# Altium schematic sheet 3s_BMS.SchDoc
size A4; SheetNumber: 1; SheetTotal: 2
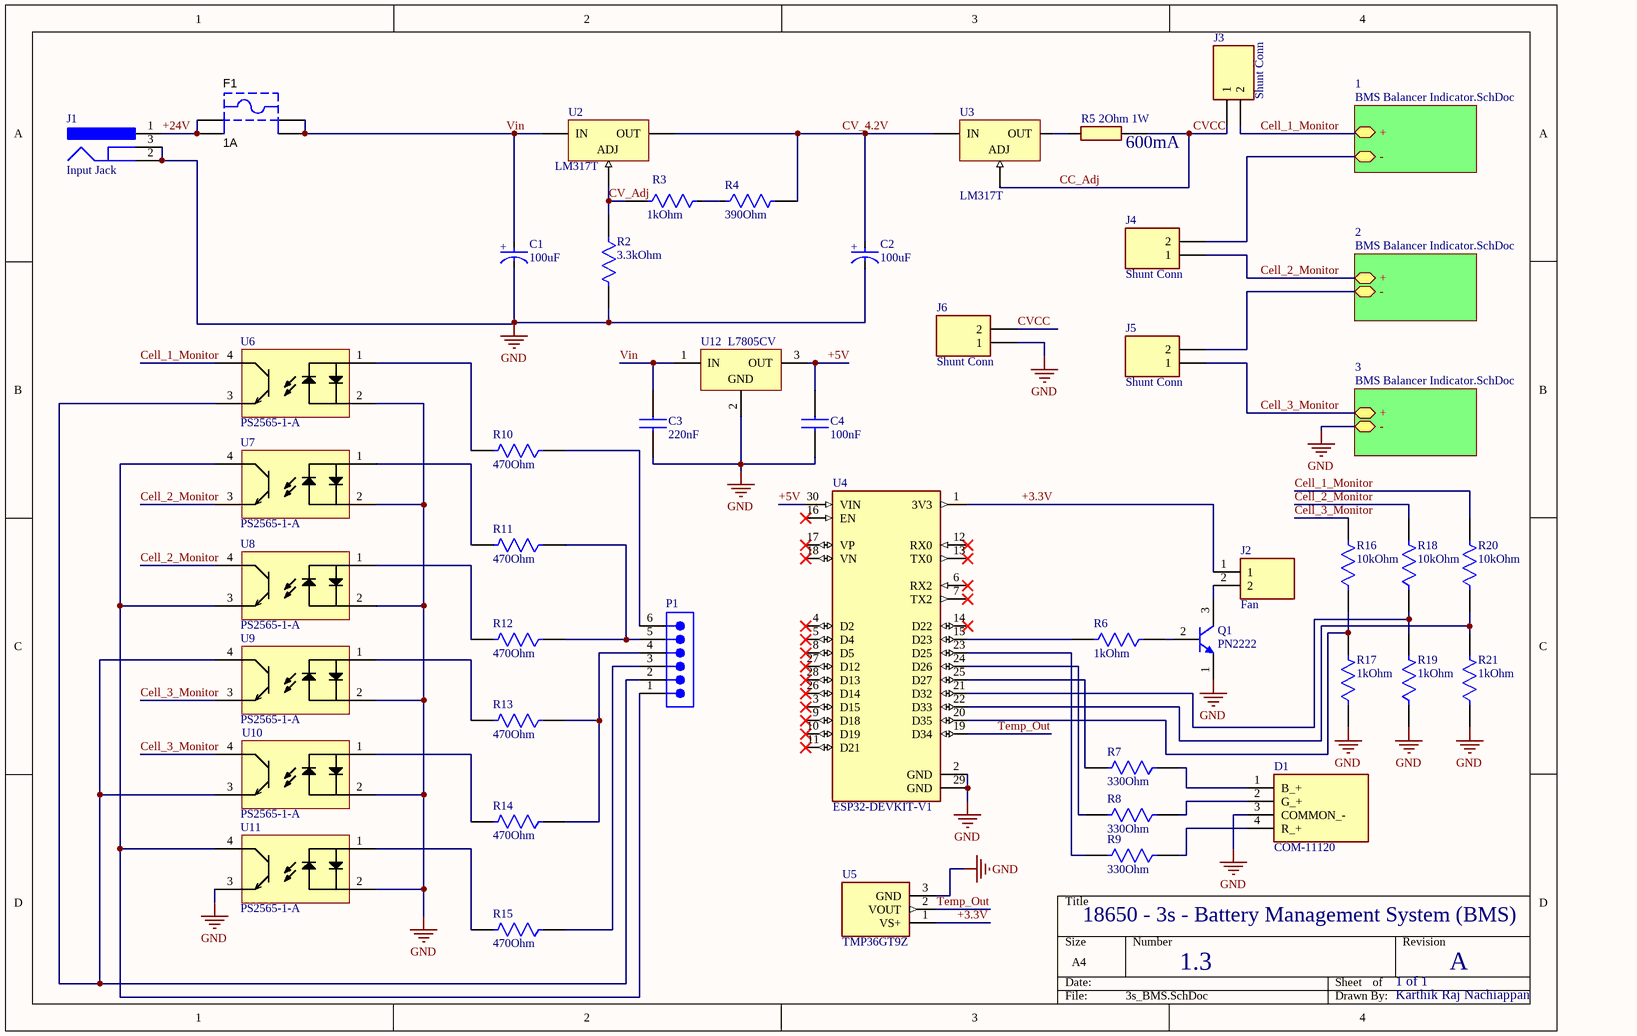
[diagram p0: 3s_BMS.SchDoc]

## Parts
C1  100uF  [FP-RAD-TH-D_8_0_5-L_11_5-MFG]
C2  100uF  [FP-RAD-TH-D_8_0_5-L_11_5-MFG]
C3  220nF  [K224K20X7RF5TH5]
C4  100nF  [C322C104K1R5TA]
D1  COM-11120  [COM11120]
F1  1A  [KSTN-3557-2]
J1  Input Jack  [CUI-PJ-002A_V]
J2  Fan  [HDRV2W67P0X254_1X2_467X234X823P]
J3  Shunt Conn  [HDRV2W67P0X254_1X2_467X234X823P]
J4  Shunt Conn  [HDRV2W67P0X254_1X2_467X234X823P]
J5  Shunt Conn  [HDRV2W67P0X254_1X2_467X234X823P]
J6  Shunt Conn  [HDRV2W67P0X254_1X2_467X234X823P]
P1  (no value)  [SMTC-TSW-106-07-X-S]
Q1  PN2222  [FAIR-TO-92-3]
R2  3.3kOhm  [FP-MRS25-MFG]
R3  1kOhm  [FP-MRS25-MFG]
R4  390Ohm  [FP-MRS25-MFG]
R5  2Ohm 1W  [RESAD1650W63L650D250]
R6  1kOhm  [FP-MRS25-MFG]
R7  330Ohm  [FP-MRS25-MFG]
R8  330Ohm  [FP-MRS25-MFG]
R9  330Ohm  [FP-MRS25-MFG]
R10  470Ohm  [FP-MRS25-MFG]
R11  470Ohm  [FP-MRS25-MFG]
R12  470Ohm  [FP-MRS25-MFG]
R13  470Ohm  [FP-MRS25-MFG]
R14  470Ohm  [FP-MRS25-MFG]
R15  470Ohm  [FP-MRS25-MFG]
R16  10kOhm  [FP-MRS25-MFG]
R17  1kOhm  [FP-MRS25-MFG]
R18  10kOhm  [FP-MRS25-MFG]
R19  1kOhm  [FP-MRS25-MFG]
R20  10kOhm  [FP-MRS25-MFG]
R21  1kOhm  [FP-MRS25-MFG]
U2  LM317T  [TO-220]
U3  LM317T  [TO-220]
U4  ESP32-DEVKIT-V1  [MODULE_ESP32_DEVKIT_V1]
U5  TMP36GT9Z  [TO-92]
U6  PS2565-1-A  [DIP762W50P254L460H455Q4B]
U7  PS2565-1-A  [DIP762W50P254L460H455Q4B]
U8  PS2565-1-A  [DIP762W50P254L460H455Q4B]
U9  PS2565-1-A  [DIP762W50P254L460H455Q4B]
U10  PS2565-1-A  [DIP762W50P254L460H455Q4B]
U11  PS2565-1-A  [DIP762W50P254L460H455Q4B]
U12  L7805CV  [TO220]

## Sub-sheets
1 = BMS Balancer Indicator.SchDoc: + (bidir), - (bidir)
2 = BMS Balancer Indicator.SchDoc: + (bidir), - (bidir)
3 = BMS Balancer Indicator.SchDoc: + (bidir), - (bidir)

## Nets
GND: C1.1(C) C2.1(C) C3.2 C4.2(-) D1.3(COMMON_-) J1.2 J1.3 J6.1 Q1.1(E) R2.2 R17.1 R19.1 R21.1 U4.2(GND) U4.29(GND) U5.3(GND) U6.2(Cathode) U7.2(Cathode) U8.2(Cathode) U9.2(Cathode) U10.2(Cathode) U11.2(Cathode) U11.3(Emitter) U12.2(GND) ; sheet 3/-
+3.3V: J2.1 U4.1(3V3) U5.1(VS+)
+5V: C4.1(+) U4.30(VIN) U12.3(OUT)
+24V: F1.1 F1.2 J1.1
CC_Adj: J3.1 J6.2 R5.2 U3.1(ADJ)  [also labelled CVCC]
Cell_1_Monitor: J3.2 R20.2 U6.4(Collector) ; sheet 1/+
Cell_2_Monitor: J4.1 R18.2 U7.3(Emitter) U8.4(Collector) ; sheet 2/+
Cell_3_Monitor: J5.1 R16.2 U9.3(Emitter) U10.4(Collector) ; sheet 3/+
CV_4.2V: C2.2(A) R4.2 U2.2(OUT) U3.3(IN)
CV_Adj: R2.1 R3.1 U2.1(ADJ)
Temp_Out: U4.19(D34) U5.2(VOUT)
Vin: C1.2(A) C3.1 F1.3 F1.4 U2.3(IN) U12.1(IN)
NetD1_1: D1.1(B_+) R7.1
NetD1_2: D1.2(G_+) R8.1
NetD1_4: D1.4(R_+) R9.1
NetJ2_2: J2.2 Q1.3(C)
NetJ4_2: J4.2 ; sheet 1/-
NetJ5_2: J5.2 ; sheet 2/-
NetP1_1: P1.1 U7.4(Collector) U8.3(Emitter) U11.4(Collector)
NetP1_2: P1.2 U6.3(Emitter) U9.4(Collector) U10.3(Emitter)
NetP1_3: P1.3 R15.1
NetP1_4: P1.4 R13.1 R14.1
NetP1_5: P1.5 R11.1 R12.1
NetP1_6: P1.6 R10.1
NetQ1_2: Q1.2(B) R6.1
NetR3_2: R3.2 R4.1
NetR5_1: R5.1 U3.2(OUT)
NetR6_2: R6.2 U4.15(D23)
NetR7_2: R7.2 U4.25(D27)
NetR8_2: R8.2 U4.24(D26)
NetR9_2: R9.2 U4.23(D25)
NetR10_2: R10.2 U6.1(Anode)
NetR11_2: R11.2 U7.1(Anode)
NetR12_2: R12.2 U8.1(Anode)
NetR13_2: R13.2 U9.1(Anode)
NetR14_2: R14.2 U10.1(Anode)
NetR15_2: R15.2 U11.1(Anode)
NetR16_1: R16.1 R17.2 U4.20(D35)
NetR18_1: R18.1 R19.2 U4.21(D32)
NetR20_1: R20.1 R21.2 U4.22(D33)

Not connected (* = marked no-connect by the designer): U4 3(D15)* 4(D2)* 5(D4)* 6(RX2)* 7(TX2)* 8(D5)* 9(D18)* 10(D19)* 11(D21)* 12(RX0)* 13(TX0)* 14(D22)* 16(EN)* 17(VP)* 18(VN)* 26(D14)* 27(D12)* 28(D13)*

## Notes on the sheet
- (near R5) 600mA
- 18650 - 3s - Battery Management System (BMS)
- 1.3
- 1 of 1
- A
- Karthik Raj Nachiappan

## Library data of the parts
C1 C2 = CMP-05427-001978-1: Aluminum Electrolytic Capacitors (Radial Lead Type) 100uF ±20% 50V
C3 = K224K20X7RF5TH5: Capacitor; Manufacturer_Name: Vishay
C4 = C322C104M5U5TA: Capacitor; Manufacturer_Name: KEMET
D1 = COM-11120: LED; Manufacturer_Name: SparkFun
F1 = CMP-2000-05461-1: FUSE HOLDER, PCB MOUNT, 500VAC, 20A, ROHS; Manufacturer: Keystone-Electronics; Number of Circuits: 1; Voltage: 500V; Fuseholder Type: Block; Fuse Type: Blade; Fuse Size: 0.43"Lx0.15"Wx0.64"H(10.92mmx3.81mmx16.25mm); For Use With/Related Products: ATC,ATO257,MINI897; Current Rating: 30A
J1 = CMP-2000-06895-2: Through Hole Right Angle DC Power Jack, 2.5 A, 2 mm Center Pin, 3 Position, -25 to 85 degC, RoHS, Bulk; Manufacturer: CUIInc.; Brand: CUI; Inside Contact Diameter: 2mm; Voltage Rating: 24V; Outside Contact Diameter: 6.5mm; Current Rating: 2.5A; Insulation Resistance: 50MOhms
J2-J6 = 5-146277-2: Connector; Manufacturer_Name: TE Connectivity
P1 = CMP-1024-00383-1: 0.025" SQ Post Header, Through-hole, Vertical, -55 to 125 degC, 2.54 mm Pitch, 6-Pin, Male, RoHS; Manufacturer: Samtec; PartNumber: TSW-106-07-G-S; Pitch: 2.54 mm
Q1 = CMP-2000-06911-1: NPN General-Purpose Amplifier, 40 V, -55 to 150 degC, 3-Pin TO-92, RoHS, Tape and Reel; Manufacturer: FairchildSemiconductor; Configuration: Single; Collector-Emitter Saturation Voltage: 1V; Collector- Emitter Voltage VCEO Max: 40V; Unit Weight: 0.008466oz; Maximum DC Collector Current: 1A; DC Collector/Base Gain hfe Min: 100; Emitter- Base Voltage VEBO: 6V; Maximum Power Dissipation: 625mW; DC Current Gain hFE Max: 300; Gain Bandwidth Product fT: 300MHz; Collector- Base Voltage VCBO: 75V
R2-R4 R6-R21 = CMP-02408-000051-1: RES 1K OHM 0.6W 1% AXIAL; Power Rating: 600mW; Lead Diameter: 0.6mm; Voltage Rating (DC): 350V; Resistance: 1kR; Temperature Coefficient: 50ppm/°C
R5 = PR01000102008JR500: Resistor; Manufacturer_Name: Vishay
U2 U3 = CMP-0244-00444-1: 1.5A, 1.2V to 37V Adjustable Voltage Regulator, 3-Pin TO-220
U4 = CMP-027-000000-1: Dual core, Wi-Fi: 2.4 GHz up to 150 Mbits/s,BLE (Bluetooth Low Energy) and legacy Bluetooth, 32 bits, Up to 240 MHz; MF: Do it
U5 = TMP36GT9Z: Thermistor; Manufacturer_Name: Analog Devices
U6-U11 = CMP-00572-25674254-1: PS2565-1-A Optocoupler AC-IN 1-CH Transistor DC-OUT 4-Pin PDIP Magazine; Number of Elements: 1; Isolation Voltage: 5kV; Collector Emitter Voltage (VCEO): 300mV; Forward Current: 80mA; Output Current per Channel: 50mA; Output Voltage: 80V; Current Transfer Ratio: 400%; Forward Voltage: 1.4V; Rise Time: 3µs; Max Power Dissipation: 150mW
U12 = CMP-0244-00483-1: Positive Voltage Regulator, 5V, 3-Pin TO-220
